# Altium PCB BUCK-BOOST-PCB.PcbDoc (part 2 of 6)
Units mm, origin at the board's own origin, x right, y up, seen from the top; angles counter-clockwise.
Board outline 99.9 x 67.48 mm, 4 copper layers (Top Layer, POWER, GND, Bottom Layer); 181 components, 110 nets, 560 pads, 389 vias.
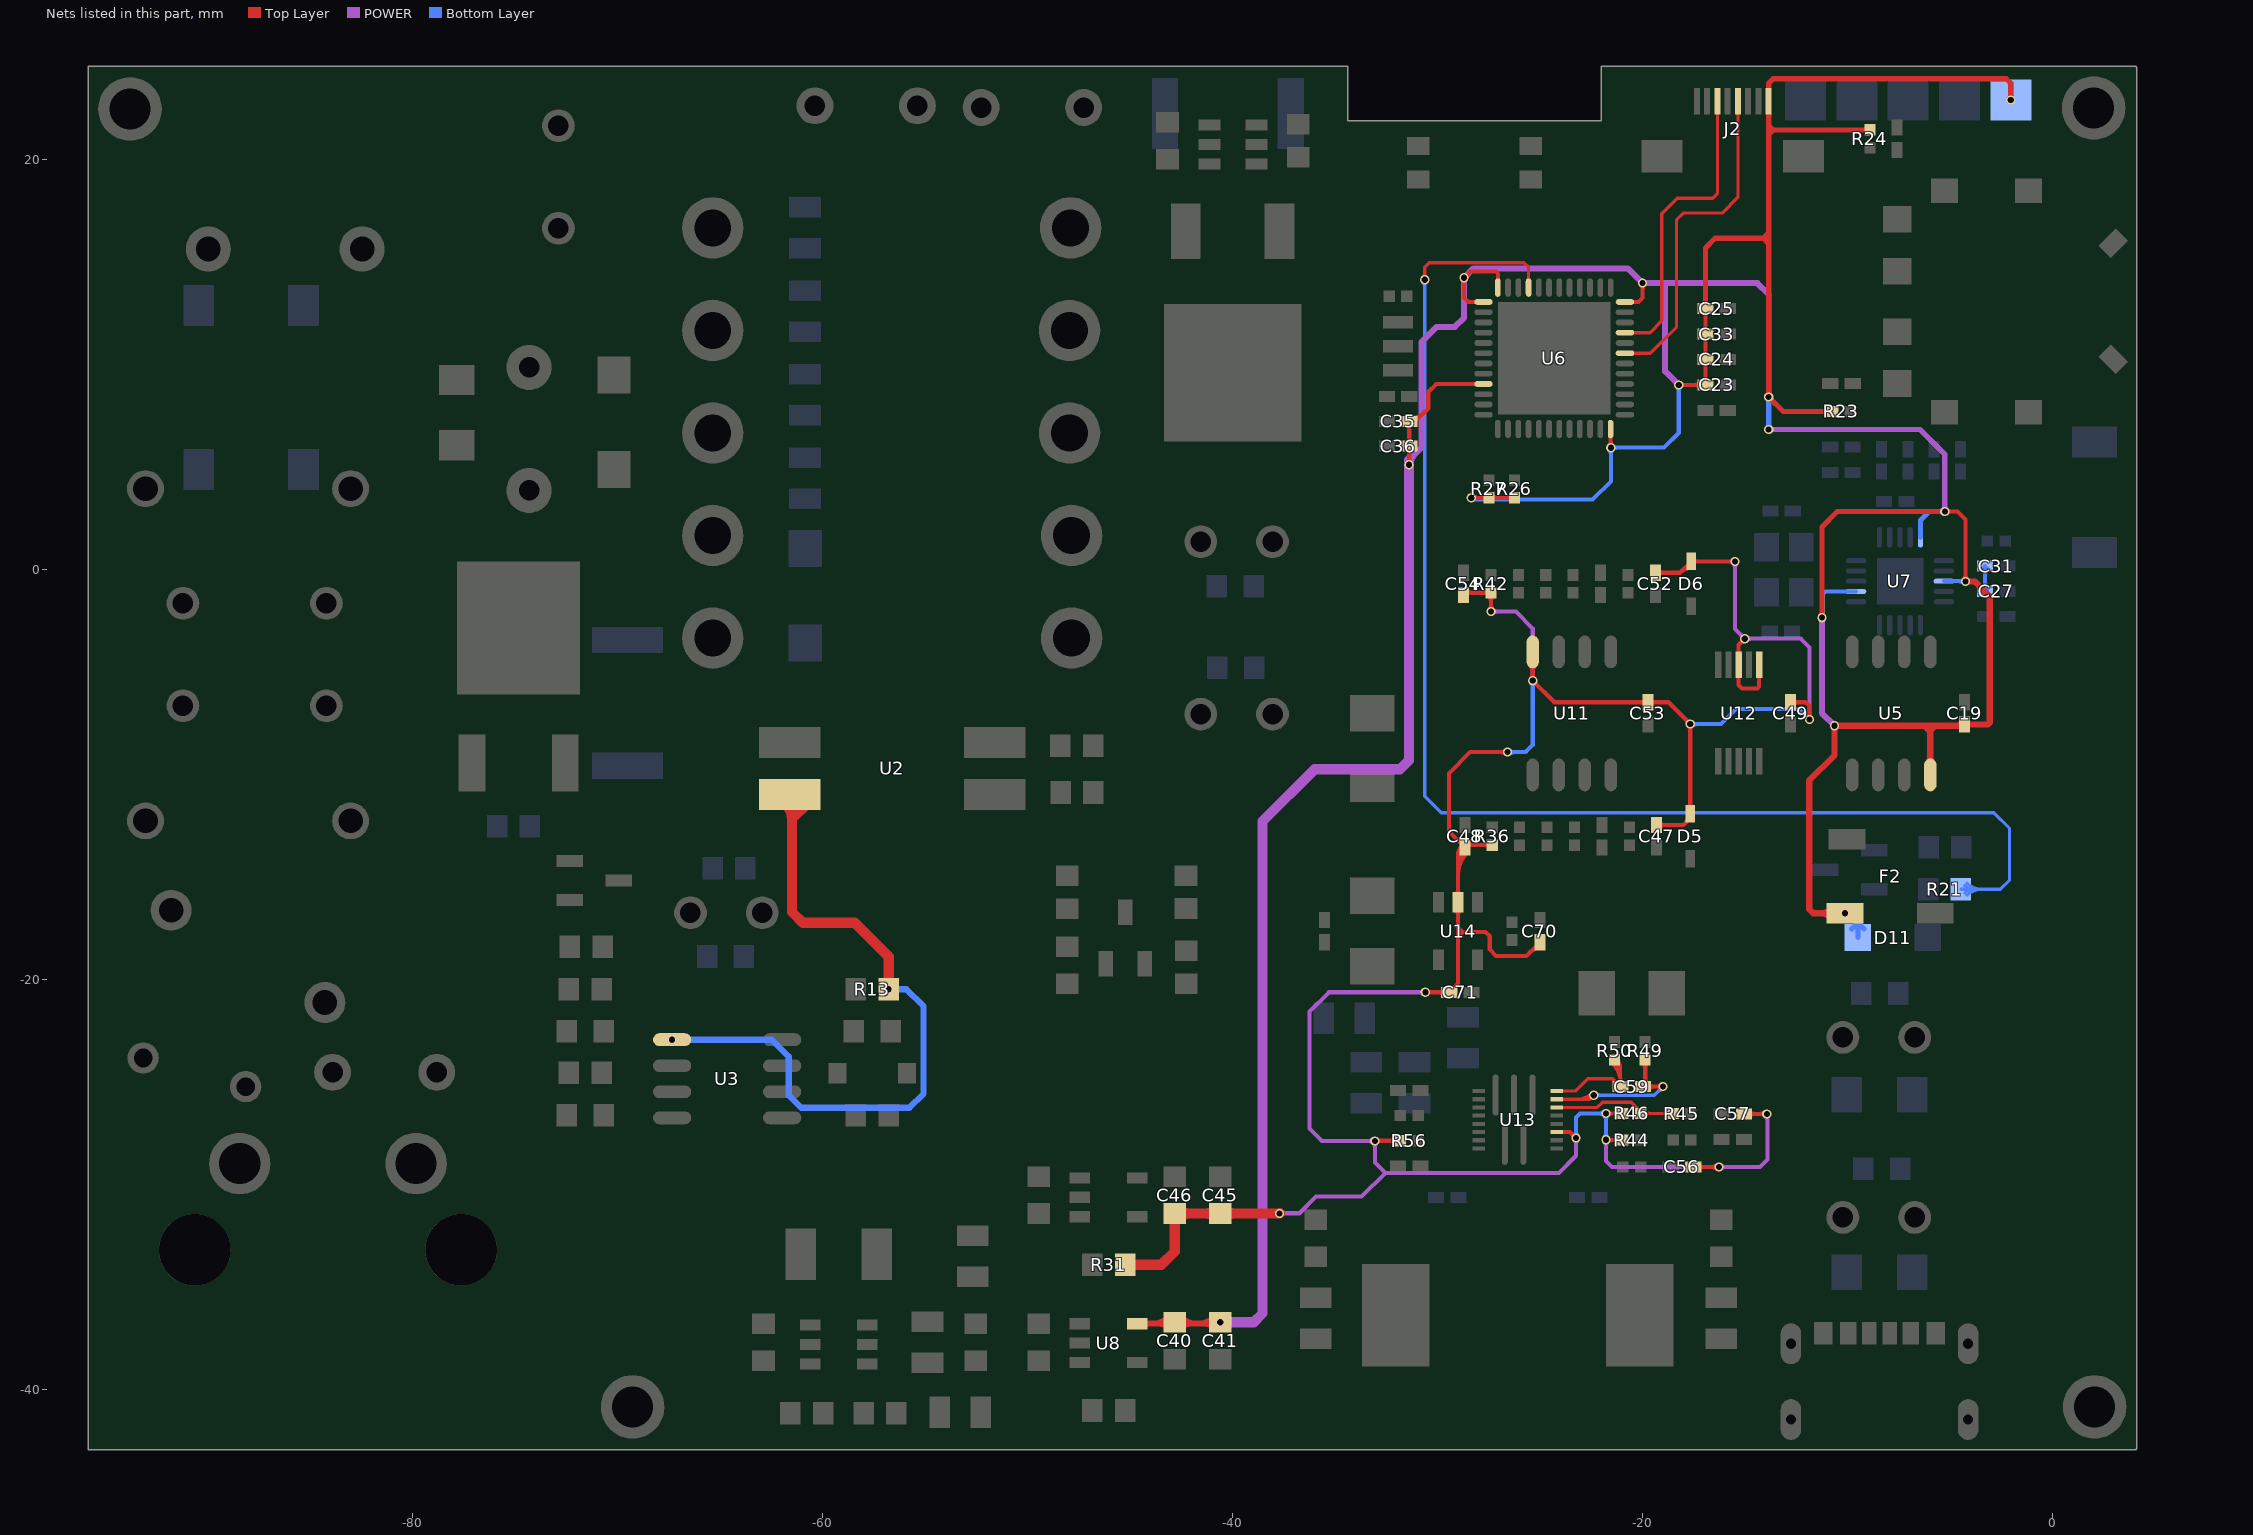
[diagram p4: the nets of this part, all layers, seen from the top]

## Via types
v1: diameter 0.45, hole 0.3, Top Layer to Bottom Layer, 389 vias

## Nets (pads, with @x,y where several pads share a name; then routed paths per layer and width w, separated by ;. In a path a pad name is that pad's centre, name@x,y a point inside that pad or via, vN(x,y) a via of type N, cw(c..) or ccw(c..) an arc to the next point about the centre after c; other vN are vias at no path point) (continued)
AGND: C45.1 C46.1 C47.1 C48.1 C49.2 C52.2 C53.2 C54.1 C56.2 C57.1 C70.2 C71.1 D5.2 D6.2 R31.1 R36.1 R42.1 R44.2 R46.1 R56.2 U11.4 U12.1 U12.3 U13.16 U14.2 | length 184.5
  Top Layer w0.2: v1(-33.044,-27.855) -33.037,-27.848 R56.2@-31.8,-27.848 ; v1@-32.956,-27.943 cw(c-32.726,-28.173) -32.726,-27.848 ; v1@-32.956,-27.766 ccw(c-32.759,-27.569) -32.759,-27.848 ; R56.2@-31.933,-27.968 ccw(c-32.224,-28.258) -32.224,-27.848 ccw(c-32.224,-27.438) R56.2@-31.933,-27.728 ; v1@-30.601,-20.588 v1(-30.582,-20.607) C71.1@-29.42,-20.607 -28.989,-20.176 ; v1@-30.493,-20.695 cw(c-30.28,-20.909) -30.28,-20.607 cw(c-30.28,-20.305) v1@-30.493,-20.519 ; C71.1@-29.665,-20.727 ccw(c-29.956,-21.017) -29.956,-20.607 ccw(c-29.956,-20.197) C71.1@-29.665,-20.487 ; C71.1@-29.127,-20.584 cw(c-28.646,-20.519) -28.989,-20.176 ; U14.2@-29.113,-16.572 cw(c-29.411,-16.871) -28.989,-16.871 cw(c-28.566,-16.871) U14.2@-28.865,-16.572 ; U14.2@-29.113,-15.875 ccw(c-29.411,-15.576) -28.989,-15.576 ccw(c-28.566,-15.576) U14.2@-28.865,-15.875 ; -28.989,-14.877 cw(c-27.443,-14.877) C48.1@-28.536,-13.784 ; -28.989,-14.394 cw(c-27.925,-14.394) C48.1@-28.677,-13.642 ; -28.989,-13.912 cw(c-28.408,-13.912) C48.1@-28.819,-13.501 ; C48.1@-28.723,-13.82 ccw(c-28.818,-14.042) -28.989,-13.871 ; C54.1@-28.722,-1.234 -28.61,-1.121 R42.1@-27.385,-1.121 -27.385,-2.026 v1(-27.376,-2.034) ; C54.1@-28.602,-1.229 cw(c-28.343,-1.488) -28.343,-1.121 ; C54.1@-28.602,-0.988 ccw(c-28.281,-0.667) -28.281,-1.121 ; C48.1@-28.536,-13.534 cw(c-28.277,-13.793) -28.277,-13.426 ; C48.1@-28.536,-13.293 ccw(c-28.215,-12.972) -28.215,-13.426 ; R42.1@-27.505,-1.254 cw(c-27.795,-1.545) -27.385,-1.545 cw(c-26.974,-1.545) R42.1@-27.264,-1.254 ; R42.1@-27.505,-1.242 ccw(c-27.795,-1.532) -27.795,-1.121 ccw(c-27.795,-0.711) R42.1@-27.505,-1.001 ; v1@-27.465,-1.946 ccw(c-27.657,-1.753) -27.385,-1.753 ; R36.1@-27.439,-13.547 ccw(c-27.729,-13.837) -27.729,-13.426 ccw(c-27.729,-13.016) R36.1@-27.439,-13.306 ; -27.385,-1.712 ccw(c-27.054,-1.712) v1@-27.288,-1.946 ; R36.1@-27.319,-13.426 -28.544,-13.426 C48.1@-28.656,-13.539 ; v1@-26.659,-8.982 ccw(c-26.873,-9.196) -26.873,-8.894 ccw(c-26.873,-8.592) v1@-26.659,-8.805 ; v1(-26.571,-8.894) -28.393,-8.894 -29.437,-9.938 -29.437,-12.758 C48.1@-28.656,-13.539 ; -25.504,-18.672 cw(c-25,-19.176) C70.2@-25,-18.464 ; U11.4@-25.487,-4.646 cw(c-25.828,-4.988) -25.345,-4.988 cw(c-24.863,-4.988) U11.4@-25.204,-4.646 ; v1@-25.434,-5.319 ccw(c-25.647,-5.106) -25.345,-5.106 ccw(c-25.044,-5.106) v1@-25.257,-5.319 ; v1@-25.345,-5.533 cw(c-25.345,-5.834) -25.132,-5.621 cw(c-24.919,-5.408) v1@-25.22,-5.408 ; U11.4@-25.345,-4.006 v1(-25.345,-5.408) -24.293,-6.46 C53.2@-19.726,-6.46 -18.73,-6.46 v1(-17.662,-7.528) D5.2@-17.662,-11.896 -17.662,-12.108 -18.002,-12.448 C47.1@-19.301,-12.448 ; C70.2@-25,-18.169 -25.659,-18.828 -27.135,-18.828 -27.439,-18.524 -27.439,-17.875 -27.648,-17.666 -28.773,-17.666 ; U13.16@-24.178,-27.422 -23.524,-27.422 v1(-23.232,-27.714) ; v1@-23.357,-27.714 ccw(c-23.659,-27.714) -23.445,-27.5 ccw(c-23.232,-27.287) v1@-23.232,-27.589 ; v1(-21.775,-26.515) R46.1@-20.948,-26.515 ; v1(-21.774,-27.8) -21.754,-27.82 R44.2@-20.948,-27.82 ; v1@-21.687,-26.603 cw(c-21.474,-26.817) -21.474,-26.515 cw(c-21.474,-26.213) v1@-21.687,-26.427 ; v1@-21.686,-27.889 cw(c-21.52,-28.055) -21.52,-27.82 ; v1@-21.686,-27.712 ccw(c-21.425,-27.451) -21.425,-27.82 ; R44.2@-21.081,-27.94 ccw(c-21.371,-28.23) -21.371,-27.82 ccw(c-21.371,-27.409) R44.2@-21.081,-27.7 ; R46.1@-21.081,-26.635 ccw(c-21.371,-26.925) -21.371,-26.515 ccw(c-21.371,-26.105) R46.1@-21.081,-26.395 ; C53.2@-19.846,-6.58 ccw(c-20.136,-6.871) -20.136,-6.46 ccw(c-20.136,-6.05) C53.2@-19.846,-6.34 ; C53.2@-19.605,-6.58 cw(c-19.315,-6.871) -19.315,-6.46 cw(c-19.315,-6.05) C53.2@-19.605,-6.34 ; C52.2@-19.359,-0.143 -18.162,-0.143 D6.2@-17.61,0.409 v1(-15.475,0.409) v1@-15.458,0.392 ; C52.2@-19.238,-0.264 cw(c-18.948,-0.554) -18.948,-0.143 cw(c-18.948,0.267) C52.2@-19.238,-0.023 ; C47.1@-19.181,-12.569 cw(c-18.891,-12.859) -18.891,-12.448 cw(c-18.891,-12.038) C47.1@-19.181,-12.328 ; -18.16,-0.142 cw(c-17.61,-0.692) D6.2@-17.61,0.087 ; -17.892,-12.338 ccw(c-18.138,-12.091) D5.2@-17.789,-12.091 ; D5.2@-17.85,-12.297 cw(c-17.662,-12.485) D5.2@-17.662,-12.219 ; v1@-17.787,-7.528 ccw(c-18.089,-7.528) -17.875,-7.315 ccw(c-17.662,-7.102) v1@-17.662,-7.403 ; D5.2@-17.752,-11.611 ccw(c-17.97,-11.393) -17.662,-11.393 ccw(c-17.354,-11.393) D5.2@-17.572,-11.611 ; v1@-17.75,-7.617 cw(c-17.964,-7.83) -17.662,-7.83 cw(c-17.36,-7.83) v1@-17.574,-7.617 ; C56.2@-17.519,-29.125 v1(-16.265,-29.125) v1@-16.26,-29.13 ; D6.2@-17.52,0.319 cw(c-17.302,0.101) -17.302,0.409 cw(c-17.302,0.717) D6.2@-17.52,0.499 ; C56.2@-17.274,-29.245 cw(c-16.984,-29.535) -16.984,-29.125 cw(c-16.984,-28.714) C56.2@-17.274,-29.005 ; v1@-16.353,-29.213 ccw(c-16.567,-29.427) -16.567,-29.125 ccw(c-16.567,-28.823) v1@-16.353,-29.036 ; v1@-15.563,0.321 ccw(c-15.777,0.107) -15.777,0.409 ccw(c-15.777,0.711) v1@-15.563,0.497 ; v1@-15.13,-3.362 cw(c-15.432,-3.362) -15.218,-3.575 cw(c-15.005,-3.788) v1@-15.005,-3.487 ; C57.1@-15.048,-26.537 v1(-13.926,-26.537) ; v1(-15.005,-3.362) -15.299,-3.656 U12.3@-15.299,-4.637 -15.299,-5.619 -15.136,-5.782 -14.389,-5.782 -14.3,-5.693 U12.1@-14.3,-4.637 ; C57.1@-14.803,-26.657 cw(c-14.512,-26.947) -14.512,-26.537 cw(c-14.512,-26.126) C57.1@-14.803,-26.416 ; v1@-14.014,-26.625 ccw(c-14.227,-26.838) -14.227,-26.537 ccw(c-14.227,-26.235) v1@-14.014,-26.448 ; C49.2@-12.766,-6.46 -12.03,-6.46 -11.852,-6.638 v1(-11.852,-7.308) ; C49.2@-12.646,-6.58 cw(c-12.356,-6.871) -12.356,-6.46 cw(c-12.356,-6.05) C49.2@-12.646,-6.34 ; v1@-11.94,-7.219 ccw(c-12.153,-7.006) -11.852,-7.006 ccw(c-11.55,-7.006) v1@-11.763,-7.219 ; -28.989,-20.176 -28.989,-17.901 ; -28.989,-17.901 -28.773,-17.685 -28.773,-17.666 ; -28.989,-17.901 -28.989,-17.666 ; -28.989,-17.666 -28.773,-17.666 ; -28.989,-17.666 -28.989,-17.45 ; -28.989,-17.45 -28.773,-17.666 ; -28.989,-17.45 U14.2@-28.989,-16.224 -28.989,-13.871 ; -28.989,-13.871 C48.1@-28.656,-13.539
  Top Layer w0.5: R31.1@-45.229,-33.897 -43.457,-33.897 -42.807,-33.248 C46.1@-42.807,-31.396 C45.1@-40.587,-31.396 v1(-37.689,-31.396) v1@-37.677,-31.384 ; R31.1@-45.052,-34.075 cw(c-44.625,-34.502) -44.625,-33.897 cw(c-44.625,-33.293) R31.1@-45.052,-33.72 ; C46.1@-42.984,-31.573 cw(c-43.411,-32) -42.807,-32 cw(c-42.203,-32) C46.1@-42.63,-31.573 ; C46.1@-42.579,-31.573 cw(c-42.152,-32) -42.152,-31.396 cw(c-42.152,-30.792) C46.1@-42.579,-31.219 ; C45.1@-40.815,-31.573 ccw(c-41.242,-32) -41.242,-31.396 ccw(c-41.242,-30.792) C45.1@-40.815,-31.219 ; C45.1@-40.359,-31.573 cw(c-39.932,-32) -39.932,-31.396 cw(c-39.932,-30.792) C45.1@-40.359,-31.219
  POWER w0.2: v1@-37.677,-31.384 -36.728,-31.384 -35.916,-30.573 -33.689,-30.573 -32.536,-29.42 ; v1@-37.6,-31.484 cw(c-37.359,-31.726) -37.359,-31.384 ; v1@-37.6,-31.308 ccw(c-37.415,-31.123) -37.415,-31.384 ; v1@-33.133,-27.766 cw(c-33.346,-27.553) -33.346,-27.855 cw(c-33.346,-28.157) -33.133,-27.943 cw(c-33.346,-28.157) -33.044,-28.157 cw(c-32.742,-28.157) v1@-32.956,-27.943 ; v1@-30.67,-20.695 ccw(c-30.883,-20.909) -30.883,-20.607 ccw(c-30.883,-20.305) v1@-30.67,-20.519 ; v1(-30.582,-20.607) -35.291,-20.607 -36.231,-21.547 -36.231,-27.257 -35.632,-27.855 v1(-33.044,-27.855) -33.044,-28.912 -32.536,-29.42 ; v1(-27.376,-2.034) -26.167,-2.034 -25.345,-2.856 v1(-25.345,-5.408) ; v1@-27.288,-2.123 cw(c-27.074,-2.336) -27.074,-2.034 cw(c-27.074,-1.733) v1@-27.288,-1.946 ; v1@-25.434,-5.319 ccw(c-25.647,-5.106) -25.345,-5.106 ccw(c-25.044,-5.106) v1@-25.257,-5.319 ; v1@-23.32,-27.802 cw(c-23.534,-28.016) -23.232,-28.016 cw(c-22.93,-28.016) v1@-23.144,-27.802 ; v1(-23.232,-27.714) -23.232,-28.58 -24.072,-29.42 -32.536,-29.42 ; v1@-21.863,-27.889 cw(c-22.076,-28.102) -21.774,-28.102 cw(c-21.472,-28.102) v1@-21.686,-27.889 ; v1(-21.774,-27.8) -21.774,-28.826 -21.476,-29.125 v1(-16.265,-29.125) -14.254,-29.125 -13.893,-28.763 -13.893,-26.57 v1(-13.926,-26.537) ; v1@-16.353,-29.213 ccw(c-16.567,-29.427) -16.567,-29.125 ccw(c-16.567,-28.823) v1@-16.353,-29.036 ; v1@-16.177,-29.213 cw(c-15.963,-29.427) -15.963,-29.125 cw(c-15.963,-28.823) v1@-16.177,-29.036 ; v1@-15.563,0.321 cw(c-15.777,0.107) -15.475,0.107 cw(c-15.173,0.107) v1@-15.387,0.321 ; v1(-15.475,0.409) -15.475,-2.892 v1(-15.005,-3.362) -12.275,-3.362 -11.852,-3.785 v1(-11.852,-7.308) ; v1@-15.13,-3.362 ccw(c-15.432,-3.362) -15.218,-3.148 ccw(c-15.005,-2.935) v1@-15.005,-3.237 ; v1@-14.917,-3.45 cw(c-14.703,-3.663) -14.703,-3.362 cw(c-14.703,-3.06) v1@-14.917,-3.273 ; v1@-14.014,-26.625 cw(c-14.307,-26.918) -13.893,-26.918 ; v1@-11.94,-7.219 ccw(c-12.153,-7.006) -11.852,-7.006 ccw(c-11.55,-7.006) v1@-11.763,-7.219
  Bottom Layer w0.2: v1(-26.571,-8.894) -25.687,-8.894 -25.345,-8.552 v1(-25.345,-5.408) ; v1@-26.483,-8.982 cw(c-26.269,-9.196) -26.269,-8.894 cw(c-26.269,-8.592) v1@-26.483,-8.805 ; v1@-25.434,-5.496 cw(c-25.647,-5.709) -25.345,-5.709 cw(c-25.044,-5.709) v1@-25.257,-5.496 ; v1@-23.32,-27.625 ccw(c-23.534,-27.412) -23.232,-27.412 ccw(c-22.93,-27.412) v1@-23.144,-27.625 ; v1(-23.232,-27.714) -23.232,-26.712 -23.035,-26.515 v1(-21.775,-26.515) -21.775,-27.799 v1(-21.774,-27.8) ; v1@-21.864,-26.427 cw(c-22.077,-26.213) -22.077,-26.515 cw(c-22.077,-26.817) -21.864,-26.603 cw(c-22.077,-26.817) -21.775,-26.817 cw(c-21.474,-26.817) v1@-21.687,-26.603 ; v1@-21.863,-27.712 ccw(c-22.073,-27.502) -21.775,-27.502 ; -21.775,-27.495 ccw(c-21.469,-27.495) v1@-21.686,-27.712 ; v1(-17.662,-7.528) -16.166,-7.528 -15.432,-6.794 -12.365,-6.794 v1(-11.852,-7.308) ; v1@-17.574,-7.617 cw(c-17.36,-7.83) -17.36,-7.528 cw(c-17.36,-7.227) v1@-17.574,-7.44 ; v1@-11.977,-7.308 ccw(c-12.278,-7.308) -12.065,-7.094 ccw(c-11.852,-6.881) v1@-11.852,-7.183
BUZZ: R21.2 U6.45 | length 70.2
  Top Layer w0.16: v1@-30.716,14.249 ccw(c-30.963,14.497) -30.613,14.497 ccw(c-30.263,14.497) v1@-30.511,14.249 ; v1(-30.613,14.147) -30.613,14.755 -30.39,14.978 -25.772,14.978 -25.546,14.752 U6.45@-25.546,13.763 ; U6.45@-25.588,14.115 ccw(c-25.691,14.218) -25.546,14.218 ccw(c-25.401,14.218) U6.45@-25.504,14.115
  Bottom Layer w0.16: v1@-30.716,14.044 cw(c-30.963,13.797) -30.613,13.797 cw(c-30.263,13.797) v1@-30.511,14.044 ; v1(-30.613,14.147) -30.613,-11.049 -29.811,-11.852 -2.857,-11.852 -2.092,-12.617 -2.092,-15.142 -2.535,-15.585 R21.2@-4.458,-15.585 ; R21.2@-4.274,-15.769 cw(c-3.829,-16.214) -3.829,-15.585 cw(c-3.829,-14.957) R21.2@-4.274,-15.401 ; R21.2@-4.16,-15.883 cw(c-3.443,-16.6) -3.443,-15.585 cw(c-3.443,-14.57) R21.2@-4.16,-15.288
COMP: R13.1 U2.4 U3.1 | length 37.9
  Top Layer w0.5: U2.4@-61.869,-11.366 cw(c-62.44,-12.151) -61.469,-12.151 ; -61.469,-11.912 cw(c-60.624,-11.912) U2.4@-61.222,-11.315 ; U2.4@-61.469,-10.961 -61.469,-12.146 ; U2.4@-60.701,-11.402 -60.725,-11.402 -61.469,-12.146 ; R13.1@-56.936,-20.231 ccw(c-57.363,-19.803) -56.759,-19.803 ccw(c-56.154,-19.803) R13.1@-56.582,-20.231 ; v1(-56.759,-20.458) -56.759,-18.875 -58.415,-17.219 -60.941,-17.219 -61.469,-16.69 -61.469,-12.146
  Bottom Layer w0.3: v1(-67.317,-22.92) -62.456,-22.92 -61.631,-23.745 -61.631,-25.632 -61.022,-26.241 -55.749,-26.241 -55.052,-25.543 -55.052,-21.295 -55.889,-20.458 v1(-56.759,-20.458)
CS: J2.4 U6.31 | length 16.9
  Top Layer w0.16: U6.31@-20.847,10.563 -19.607,10.563 -18.333,11.836 -18.333,17.07 -18.005,17.398 -16.1,17.398 -15.338,18.16 J2.4@-15.338,22.85 ; U6.31@-20.495,10.52 cw(c-20.392,10.418) -20.392,10.563 cw(c-20.392,10.707) U6.31@-20.495,10.605 ; J2.4@-15.387,22.301 cw(c-15.507,22.181) -15.338,22.181 cw(c-15.169,22.181) J2.4@-15.288,22.301
CSN: C59.2 R49.1 U13.20 | length 13
  Top Layer w0.16: U13.20@-24.178,-25.822 -22.562,-25.822 ; -23.19,-25.822 ccw(c-23.19,-24.802) v1@-22.468,-25.523 ; -22.804,-25.822 ccw(c-22.804,-25.188) v1@-22.355,-25.637 ; v1@-22.509,-25.652 cw(c-22.699,-25.686) -22.562,-25.822 ; v1@-22.392,-25.769 ccw(c-22.426,-25.959) -22.562,-25.822 ; v1(-22.366,-25.626) -22.562,-25.822
  Top Layer w0.2: R49.1@-19.979,-24.03 cw(c-20.269,-24.321) -19.859,-24.321 cw(c-19.449,-24.321) R49.1@-19.739,-24.03 ; C59.2@-19.965,-25.087 ccw(c-20.222,-24.83) -19.859,-24.83 ; -19.859,-24.763 ccw(c-19.402,-24.763) -19.725,-25.087 ccw(c-19.435,-24.796) -19.435,-25.207 ccw(c-19.435,-25.617) C59.2@-19.725,-25.327 ; R49.1@-19.859,-23.897 -19.859,-25.096 C59.2@-19.97,-25.207 -18.988,-25.207 v1(-18.986,-25.206) ; -19.291,-25.207 ccw(c-19.291,-24.901) v1@-19.075,-25.117 ; -19.285,-25.207 cw(c-19.285,-25.504) v1@-19.075,-25.294
  Bottom Layer w0.16: v1(-22.366,-25.626) -19.407,-25.626 v1(-18.986,-25.206) ; v1@-22.263,-25.729 cw(c-22.016,-25.976) -22.016,-25.626 cw(c-22.016,-25.276) v1@-22.263,-25.523 ; v1@-19.131,-25.206 cw(c-19.482,-25.206) -19.234,-25.453 cw(c-18.986,-25.701) v1@-18.986,-25.351
CSO: R45.1 R46.2 U13.19 | length 7.5
  Top Layer w0.16: U13.19@-24.178,-26.222 -22.197,-26.222 -21.94,-25.965 -20.549,-25.965 -20.083,-26.432 R46.2@-20.083,-26.515 -18.51,-26.515 R45.1@-18.497,-26.528 ; R46.2@-19.935,-26.649 cw(c-19.611,-26.974) -19.611,-26.515 cw(c-19.611,-26.056) R46.2@-19.935,-26.381 ; -18.999,-26.515 cw(c-18.999,-27.017) R45.1@-18.644,-26.662 ; -18.938,-26.515 ccw(c-18.938,-26.1) R45.1@-18.644,-26.393
CSP: C59.1 R50.1 U13.21 | length 9.2
  Top Layer w0.16: U13.21@-24.178,-25.422 -23.265,-25.422 -22.659,-24.817 -21.45,-24.817 ; R50.1@-21.488,-24.044 cw(c-22.521,-25.077) C59.1@-21.06,-25.077 ; R50.1@-21.375,-23.931 cw(c-22.134,-24.691) -21.06,-24.691 ; C59.1@-21.367,-25.151 ccw(c-21.686,-25.053) -21.45,-24.817 ; R50.1@-21.354,-23.897 -21.06,-24.191 C59.1@-21.06,-25.207 -21.45,-24.817 ; R50.1@-21.33,-24.099 cw(c-21.289,-24.419) -21.06,-24.191 cw(c-20.809,-23.939) R50.1@-21.164,-23.92 ; R50.1@-21.262,-23.818 cw(c-21.748,-24.305) -21.06,-24.305 ; C59.1@-21.195,-25.073 ccw(c-21.519,-24.748) -21.06,-24.748 ccw(c-20.602,-24.748) C59.1@-20.926,-25.073
D3.3V: C19.1 C23.2 C24.2 C25.2 C27.2 C31.2 C33.1 C35.1 C36.1 C40.1 C41.1 D11.1 F2.1 J2.1 pad.4 R23.2 R24.2 R26.2 R27.2 U5.8 U6.1 U6.9 U6.24 U6.36 U6.48 U7.7 U7.15 U7.18 U8.5 | length 277.4
  Top Layer w0.2: C36.1@-31.489,5.909 cw(c-31.78,5.619) -31.369,5.619 cw(c-30.959,5.619) C36.1@-31.249,5.909 ; C36.1@-31.489,6.149 ccw(c-31.78,6.439) -31.369,6.439 ccw(c-30.959,6.439) C36.1@-31.249,6.149 ; C35.1@-31.489,7.113 cw(c-31.78,6.823) -31.369,6.823 cw(c-30.959,6.823) C35.1@-31.249,7.113 ; v1@-31.469,5.212 ccw(c-31.709,5.452) -31.369,5.452 ; v1(-31.38,5.123) -31.369,5.134 C36.1@-31.369,6.029 C35.1@-31.369,7.233 -31.083,7.233 -30.439,7.877 -30.439,8.673 -30.048,9.064 U6.9@-27.746,9.064 ; -31.369,5.398 ccw(c-31.106,5.398) v1@-31.292,5.212 ; C35.1@-31.244,7.403 ccw(c-31.244,8.203) -30.679,7.637 ; v1@-28.78,14.155 cw(c-28.994,13.941) -28.692,13.941 cw(c-28.39,13.941) v1@-28.603,14.155 ; v1@-28.692,14.368 ccw(c-28.692,14.67) -28.478,14.457 ccw(c-28.265,14.243) v1@-28.567,14.243 ; v1@-28.344,3.51 v1(-28.342,3.508) R27.2@-27.479,3.508 R26.2@-26.234,3.508 ; v1@-28.253,3.42 cw(c-28.04,3.207) -28.04,3.508 cw(c-28.04,3.81) v1@-28.253,3.597 ; U6.1@-27.746,13.064 -28.487,13.064 -28.692,13.269 v1(-28.692,14.243) -28.397,14.538 -27.145,14.538 -27.047,14.44 U6.48@-27.047,13.763 ; R27.2@-27.599,3.388 ccw(c-27.889,3.098) -27.889,3.508 ccw(c-27.889,3.919) R27.2@-27.599,3.629 ; R27.2@-27.359,3.388 cw(c-27.069,3.098) -27.069,3.508 cw(c-27.069,3.919) R27.2@-27.359,3.629 ; R26.2@-26.355,3.388 ccw(c-26.645,3.098) -26.645,3.508 ccw(c-26.645,3.919) R26.2@-26.355,3.629 ; v1@-21.624,6.042 ccw(c-21.813,6.231) -21.546,6.231 ; -21.546,6.28 ccw(c-21.209,6.28) v1@-21.447,6.042 ; U6.24@-21.546,6.864 -21.546,5.964 v1(-21.535,5.954) ; U6.36@-20.847,13.064 -20.178,13.064 -19.985,13.258 v1(-19.985,13.983) ; v1@-20.073,13.894 cw(c-20.286,13.681) -19.985,13.681 cw(c-19.683,13.681) v1@-19.896,13.894 ; v1(-18.223,9.015) -18.22,9.018 C23.2@-16.922,9.018 C24.2@-16.922,10.257 C33.1@-16.922,11.497 C25.2@-16.922,12.737 ; v1@-18.135,8.926 cw(c-17.914,8.705) -17.914,9.018 ; v1@-18.135,9.103 ccw(c-17.929,9.309) -17.929,9.018 ; C23.2@-17.167,8.897 ccw(c-17.458,8.607) -17.458,9.018 ccw(c-17.458,9.428) C23.2@-17.167,9.138 ; C23.2@-17.042,9.138 ccw(c-17.333,9.428) -16.922,9.428 ccw(c-16.512,9.428) C23.2@-16.802,9.138 ; C24.2@-17.042,10.137 cw(c-17.333,9.847) -16.922,9.847 cw(c-16.512,9.847) C24.2@-16.802,10.137 ; C24.2@-17.042,10.378 ccw(c-17.333,10.668) -16.922,10.668 ccw(c-16.512,10.668) C24.2@-16.802,10.378 ; C33.1@-17.042,11.377 cw(c-17.333,11.087) -16.922,11.087 cw(c-16.512,11.087) C33.1@-16.802,11.377 ; C33.1@-17.042,11.618 ccw(c-17.333,11.908) -16.922,11.908 ccw(c-16.512,11.908) C33.1@-16.802,11.618 ; C25.2@-17.042,12.617 cw(c-17.333,12.327) -16.922,12.327 cw(c-16.512,12.327) C25.2@-16.802,12.617 ; v1(-5.245,2.84) -4.624,2.84 -4.233,2.449 v1(-4.233,-0.566) ; v1@-5.157,2.751 cw(c-4.943,2.538) -4.943,2.84 cw(c-4.943,3.142) v1@-5.157,2.928 ; v1@-4.321,-0.478 ccw(c-4.535,-0.265) -4.233,-0.265 ccw(c-3.931,-0.265) v1@-4.145,-0.478
  Top Layer w0.254: C25.2@-17.023,12.838 ccw(c-17.267,13.082) -16.922,13.082 ccw(c-16.577,13.082) C25.2@-16.821,12.838 ; C25.2@-16.922,12.737 -16.922,15.697 -16.445,16.174 -14.096,16.174 ; v1@-13.907,8.501 ccw(c-14.074,8.668) -13.838,8.668 ccw(c-13.601,8.668) v1@-13.768,8.501 ; v1@-13.838,8.333 cw(c-13.838,8.097) -13.67,8.264 cw(c-13.503,8.431) v1@-13.74,8.431 ; v1@-11.311,-2.265 ccw(c-11.478,-2.098) -11.242,-2.098 ccw(c-11.005,-2.098) v1@-11.172,-2.265 ; v1@-11.208,-2.368 v1(-11.242,-2.335) -11.242,2.091 -10.493,2.84 v1(-5.245,2.84) ; R23.2@-10.832,7.623 ccw(c-11.076,7.378) -11.076,7.724 ccw(c-11.076,8.069) R23.2@-10.832,7.825 ; R23.2@-10.718,7.724 -13.13,7.724 v1(-13.838,8.431) -13.838,15.915 ; R24.2@-8.999,21.35 ccw(c-9.243,21.106) -9.243,21.451 ccw(c-9.243,21.796) R24.2@-8.999,21.552 ; R24.2@-8.898,21.451 -13.623,21.451 ; v1@-5.314,2.77 ccw(c-5.482,2.603) -5.482,2.84 ccw(c-5.482,3.076) v1@-5.314,2.909 ; v1@-2.099,22.976 ccw(c-2.266,23.144) -2.029,23.144 ccw(c-1.793,23.144) v1@-1.96,22.976 ; v1(-2.029,22.907) -2.029,23.724 -2.249,23.943 -13.618,23.943 -13.838,23.724 J2.1@-13.838,22.85 -13.838,21.666 ; -14.096,16.174 -13.838,16.432 ; -14.096,16.174 -13.928,16.174 -13.838,16.083 ; -14.096,16.174 -13.838,15.915 ; -13.838,15.915 -13.838,16.083 ; -13.838,16.083 -13.838,16.432 ; -13.838,16.432 -13.838,21.236 ; -13.838,21.236 -13.623,21.451 ; -13.838,21.236 -13.838,21.436 ; -13.838,21.436 -13.823,21.451 -13.623,21.451 ; -13.838,21.436 -13.838,21.666 ; -13.838,21.666 -13.623,21.451
  Top Layer w0.3: U8.5@-44.631,-36.766 -40.651,-36.766 v1(-40.587,-36.702) ; U8.5@-44.317,-36.855 cw(c-44.104,-37.068) -44.104,-36.766 cw(c-44.104,-36.465) U8.5@-44.317,-36.678 ; -43.859,-36.766 ccw(c-43.859,-35.701) C40.1@-43.106,-36.454 ; -43.548,-36.766 cw(c-43.548,-37.393) C40.1@-43.106,-36.95 ; C40.1@-42.508,-36.95 cw(c-42.066,-37.393) -42.066,-36.766 ; C40.1@-42.508,-36.454 ccw(c-41.755,-35.701) -41.755,-36.766 ; -41.639,-36.766 ccw(c-41.639,-35.701) C41.1@-40.886,-36.454 ; -41.328,-36.766 cw(c-41.328,-37.393) C41.1@-40.886,-36.95 ; C41.1@-40.923,-36.766 ccw(c-40.923,-36.366) C41.1@-40.64,-36.649 ; F2.1@-10.764,-17.003 ccw(c-11.362,-17.6) -11.362,-16.755 ccw(c-11.362,-15.91) F2.1@-10.764,-16.508 ; v1(-10.117,-16.755) -11.657,-16.755 -11.855,-16.557 -11.855,-10.273 -10.625,-9.042 v1(-10.625,-7.609) -6.253,-7.609 ; U5.8@-6.06,-9.4 ccw(c-6.316,-9.143) -5.954,-9.143 ccw(c-5.592,-9.143) U5.8@-5.848,-9.4 ; U5.8@-5.954,-10.005 -5.954,-7.908 ; -5.954,-7.611 -5.954,-7.86 ; -4.709,-7.609 ccw(c-4.709,-7.12) C19.1@-4.363,-7.465 ; C19.1@-4.279,-7.609 -5.702,-7.609 ; C19.1@-4.279,-7.55 -4.277,-7.549 -3.148,-7.549 -3.054,-7.455 -3.054,-1.302 -3.79,-0.566 v1(-4.233,-0.566) ; C19.1@-4.194,-7.635 cw(c-3.985,-7.843) -3.985,-7.549 ; C19.1@-4.194,-7.465 ccw(c-3.992,-7.264) -3.992,-7.549 ; -6.253,-7.609 -5.954,-7.908 ; -6.253,-7.609 -5.702,-7.609 ; -5.954,-7.908 -5.954,-7.86 ; -5.954,-7.86 -5.702,-7.609
  POWER w0.254: v1@-13.907,8.501 ccw(c-14.074,8.668) -13.838,8.668 ccw(c-13.601,8.668) v1@-13.768,8.501 ; -13.842,13.435 -13.838,13.431 v1(-13.838,8.431) ; v1(-13.838,6.843) -6.458,6.843 -5.245,5.63 v1(-5.245,2.84) ; v1@-13.768,6.774 cw(c-13.601,6.606) -13.601,6.843 cw(c-13.601,7.079) v1@-13.768,6.912 ; v1@-5.314,2.909 ccw(c-5.482,3.076) -5.245,3.076 ccw(c-5.009,3.076) v1@-5.176,2.909
  POWER w0.3: -31.38,5.358 -30.767,5.972 -30.767,11.112 -30.035,11.844 -29.139,11.844 -28.692,12.291 v1(-28.692,14.243) -28.236,14.699 -20.701,14.699 v1(-19.985,13.983) -18.889,13.983 ; v1@-31.305,5.123 cw(c-30.557,5.123) -31.086,5.652 ; v1(-18.223,9.015) -18.889,9.68 -18.889,13.983 ; -13.842,13.435 -14.389,13.983 -18.889,13.983 ; v1(-11.242,-2.335) -11.242,-6.992 v1(-10.625,-7.609)
  POWER w0.5: v1(-40.587,-36.702) -38.956,-36.702 -38.525,-36.271 -38.525,-12.268 -35.984,-9.727 -31.819,-9.727 -31.38,-9.289 v1(-31.38,5.123) -31.38,5.358
  Bottom Layer w0.2: v1(-28.342,3.508) -28.262,3.429 -22.421,3.429 -21.535,4.314 v1(-21.535,5.954) -18.946,5.954 -18.223,6.676 v1(-18.223,9.015) ; v1@-28.253,3.597 ccw(c-27.848,4.003) -27.848,3.429 ; v1@-21.624,5.865 cw(c-21.837,5.652) -21.535,5.652 cw(c-21.234,5.652) -21.447,5.865 cw(c-21.234,5.652) -21.234,5.954 cw(c-21.234,6.256) v1@-21.447,6.042 ; v1@-18.312,8.926 cw(c-18.525,8.713) -18.223,8.713 cw(c-17.921,8.713) v1@-18.135,8.926 ; v1@-11.33,-2.246 ccw(c-11.625,-1.951) -11.208,-1.951 ; v1@-11.208,-2.368 -11.208,-1.81 -11.215,-1.804 -11.215,-1.213 -11.058,-1.057 U7.7@-9.577,-1.057 ; U7.18@-5.291,-0.557 -4.243,-0.557 v1(-4.233,-0.566) -4.223,-0.557 -3.77,-0.557 ; -4.558,-0.557 cw(c-4.558,-0.892) v1@-4.321,-0.655 ; -4.511,-0.557 ccw(c-4.511,-0.288) v1@-4.321,-0.478 ; v1@-4.145,-0.655 cw(c-3.908,-0.892) -3.908,-0.557 ; v1@-4.145,-0.478 ccw(c-3.955,-0.288) -3.955,-0.557 ; C27.2@-3.574,-1.044 ccw(c-4.243,-1.029) -3.77,-0.557 ; C27.2@-3.4,-0.927 ccw(c-3.69,-0.637) -3.279,-0.637 ccw(c-2.869,-0.637) C27.2@-3.159,-0.927 ; C31.2@-3.4,0.058 cw(c-3.69,-0.232) -3.279,-0.232 cw(c-2.869,-0.232) C31.2@-3.159,0.058 ; C31.2@-3.279,0.178 C27.2@-3.279,-1.047 -3.77,-0.557
  Bottom Layer w0.254: v1@-13.907,6.912 ccw(c-14.074,7.079) -13.838,7.079 ccw(c-13.601,7.079) v1@-13.768,6.912 ; v1@-13.907,8.362 cw(c-14.074,8.195) -13.838,8.195 cw(c-13.601,8.195) v1@-13.768,8.362 ; v1(-13.838,6.843) v1(-13.838,8.431) ; v1(-10.117,-16.755) -9.667,-16.755 -9.487,-16.935 ; v1@-10.048,-16.824 cw(c-9.88,-16.992) -9.88,-16.755 cw(c-9.88,-16.518) v1@-10.048,-16.686 ; D11.1@-9.786,-17.508 ccw(c-10.185,-16.936) -9.487,-16.936 ; D11.1@-9.487,-17.937 -9.487,-16.935 ; D11.1@-9.188,-17.508 cw(c-8.789,-16.936) -9.487,-16.936 ; U7.15@-6.434,1.586 -6.434,2.412 -6.006,2.84 v1(-5.245,2.84) ; v1@-5.314,2.77 ccw(c-5.482,2.603) -5.482,2.84 ccw(c-5.482,3.076) v1@-5.314,2.909
DC: J2.6 U6.33 | length 15.4
  Top Layer w0.16: U6.33@-20.847,11.563 -19.624,11.563 -19.053,12.134 -19.053,17.368 -18.303,18.118 -16.568,18.118 -16.338,18.348 J2.6@-16.338,22.85 ; U6.33@-20.495,11.521 cw(c-20.392,11.418) -20.392,11.563 cw(c-20.392,11.708) U6.33@-20.495,11.606 ; J2.6@-16.387,22.301 cw(c-16.507,22.181) -16.338,22.181 cw(c-16.169,22.181) J2.6@-16.288,22.301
